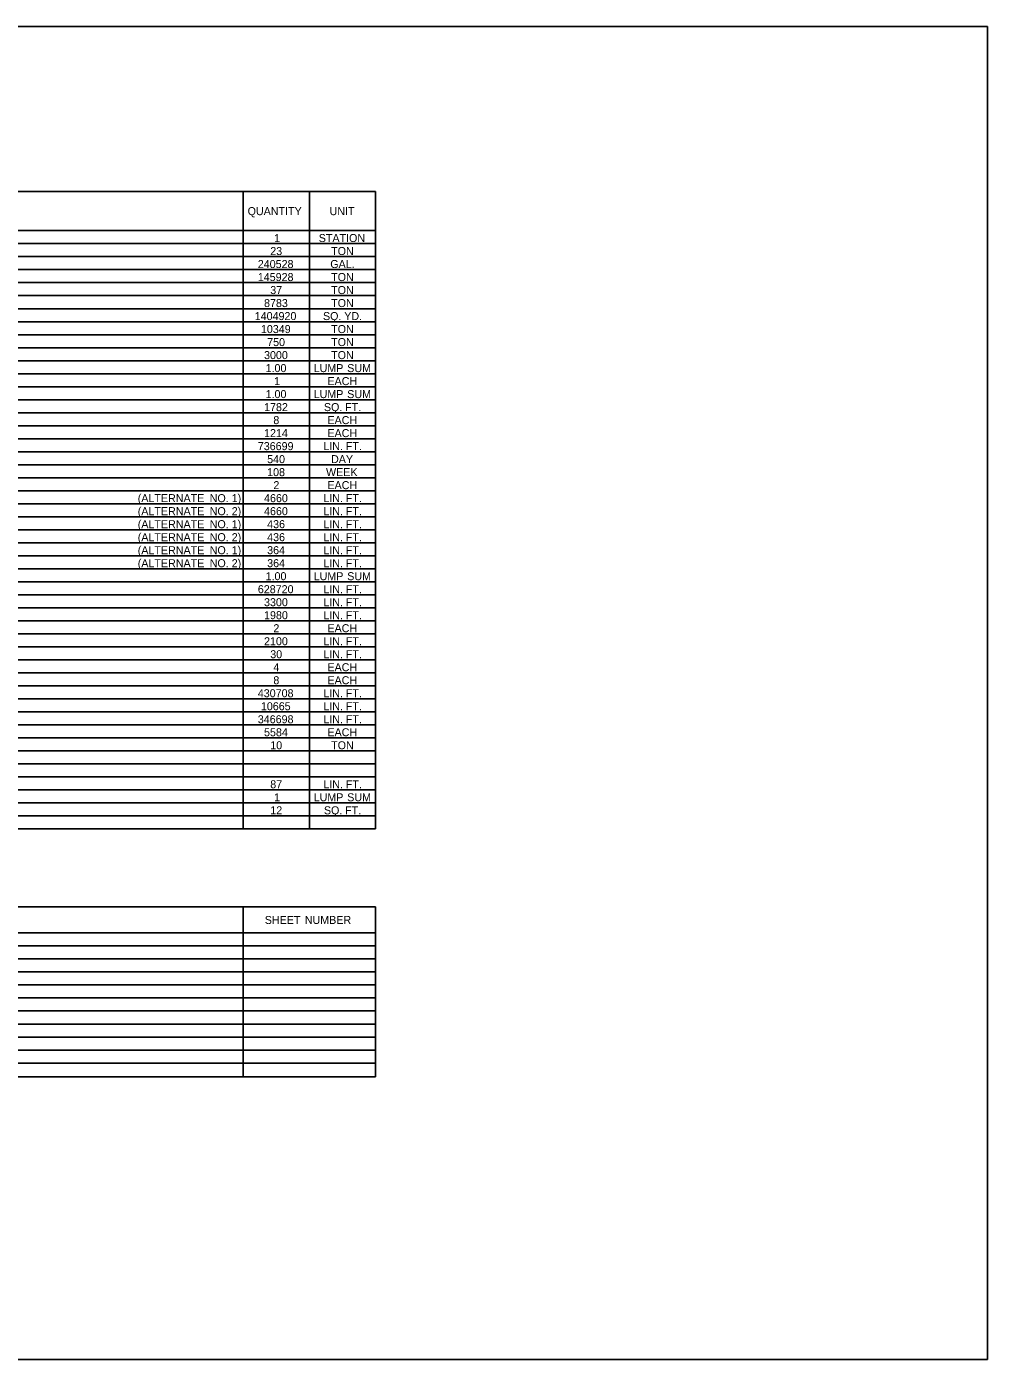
# Model space of a CAD drawing. Extents: x 2261867 to 2275370, y -3124789 to -3122260.
# Drawn here: x 2274649 to 2275370, y -3124789 to -3123790 of the extents above; entities that cross this region are included whole.
import ezdxf

# ---------------------------------------------------------------- set-up
doc = ezdxf.new("R2010")
doc.units = 0
doc.layers.add('Default', color=7, linetype='Continuous')
doc.layers.add('DSN_DRFT_Named-Boundary', color=7, linetype='Continuous')

msp = doc.modelspace()

# ---------------------------------------------------------------- linework, layer by layer
at = {"layer": 'Default'}
for p, q in [((2274241.54, -3123913.99), (2274910.87, -3123913.99)), ((2274811.42, -3123913.99), (2274910.87, -3123913.99)), ((2274811.42, -3124391.74), (2274811.42, -3123913.99)), ((2274861.15, -3124391.74), (2274861.15, -3123913.99)), ((2274861.15, -3124342.99), (2274861.15, -3123913.99)), ((2274910.87, -3124391.74), (2274910.87, -3123913.99)), ((2274241.54, -3123943.24), (2274910.87, -3123943.24)), ((2274241.54, -3123943.24), (2274910.87, -3123943.24)), ((2274811.42, -3124342.99), (2274811.42, -3123943.24)), ((2274241.54, -3123952.99), (2274910.87, -3123952.99)), ((2274241.54, -3123962.74), (2274910.87, -3123962.74)), ((2274241.54, -3123972.49), (2274910.87, -3123972.49)), ((2274241.54, -3123982.24), (2274910.87, -3123982.24)), ((2274241.54, -3123991.99), (2274910.87, -3123991.99)), ((2274241.54, -3124001.74), (2274910.87, -3124001.74)), ((2274241.54, -3124011.49), (2274910.87, -3124011.49)), ((2274241.54, -3124021.24), (2274910.87, -3124021.24)), ((2274241.54, -3124030.99), (2274910.87, -3124030.99)), ((2274241.54, -3124040.74), (2274910.87, -3124040.74)), ((2274241.54, -3124050.49), (2274910.87, -3124050.49)), ((2274241.54, -3124060.24), (2274910.87, -3124060.24)), ((2274241.54, -3124069.99), (2274910.87, -3124069.99)), ((2274241.54, -3124079.74), (2274910.87, -3124079.74)), ((2274241.54, -3124089.49), (2274910.87, -3124089.49)), ((2274241.54, -3124099.24), (2274910.87, -3124099.24)), ((2274241.54, -3124108.99), (2274910.87, -3124108.99)), ((2274241.54, -3124118.74), (2274910.87, -3124118.74)), ((2274241.54, -3124128.49), (2274910.87, -3124128.49)), ((2274241.54, -3124138.24), (2274910.87, -3124138.24)), ((2274241.54, -3124147.99), (2274910.87, -3124147.99)), ((2274241.54, -3124157.74), (2274910.87, -3124157.74)), ((2274241.54, -3124167.49), (2274910.87, -3124167.49)), ((2274241.54, -3124177.24), (2274910.87, -3124177.24)), ((2274241.54, -3124186.99), (2274910.87, -3124186.99)), ((2274241.54, -3124196.74), (2274910.87, -3124196.74)), ((2274241.54, -3124206.49), (2274910.87, -3124206.49)), ((2274241.54, -3124216.24), (2274910.87, -3124216.24)), ((2274241.54, -3124225.99), (2274910.87, -3124225.99)), ((2274241.54, -3124235.74), (2274910.87, -3124235.74)), ((2274241.54, -3124245.49), (2274910.87, -3124245.49)), ((2274241.54, -3124255.24), (2274910.87, -3124255.24)), ((2274241.54, -3124264.99), (2274910.87, -3124264.99)), ((2274241.54, -3124274.74), (2274910.87, -3124274.74)), ((2274241.54, -3124284.49), (2274910.87, -3124284.49)), ((2274241.54, -3124294.24), (2274910.87, -3124294.24)), ((2274241.54, -3124303.99), (2274910.87, -3124303.99)), ((2274241.54, -3124313.74), (2274910.87, -3124313.74)), ((2274241.54, -3124323.49), (2274910.87, -3124323.49)), ((2274241.54, -3124333.24), (2274910.87, -3124333.24)), ((2274241.54, -3124342.99), (2274910.87, -3124342.99)), ((2274861.15, -3124342.99), (2274910.87, -3124342.99)), ((2274241.54, -3124352.74), (2274910.87, -3124352.74)), ((2274241.54, -3124352.74), (2274910.87, -3124352.74)), ((2274811.42, -3124391.74), (2274811.42, -3124352.74)), ((2274861.15, -3124391.74), (2274861.15, -3124352.74)), ((2274241.54, -3124362.49), (2274910.87, -3124362.49)), ((2274241.54, -3124372.24), (2274910.87, -3124372.24)), ((2274241.54, -3124381.99), (2274910.87, -3124381.99)), ((2274241.54, -3124391.74), (2274910.87, -3124391.74)), ((2274910.87, -3124391.74), (2274910.87, -3124381.99)), ((2274241.54, -3124450.24), (2274910.87, -3124450.24)), ((2274811.42, -3124450.24), (2274910.87, -3124450.24)), ((2274811.42, -3124469.74), (2274811.42, -3124450.24)), ((2274811.42, -3124577.48), (2274811.42, -3124450.24)), ((2274910.87, -3124577.48), (2274910.87, -3124450.24)), ((2274910.87, -3124577.48), (2274910.87, -3124450.24)), ((2274241.54, -3124469.74), (2274910.87, -3124469.74)), ((2274241.54, -3124479.49), (2274910.87, -3124479.49)), ((2274241.54, -3124489.24), (2274910.87, -3124489.24)), ((2274241.54, -3124498.99), (2274910.87, -3124498.99)), ((2274241.54, -3124508.74), (2274910.87, -3124508.74)), ((2274241.54, -3124518.49), (2274910.87, -3124518.49)), ((2274241.54, -3124528.24), (2274910.87, -3124528.24)), ((2274241.54, -3124537.99), (2274910.87, -3124537.99)), ((2274241.54, -3124547.74), (2274910.87, -3124547.74)), ((2274241.54, -3124557.49), (2274910.87, -3124557.49)), ((2274241.54, -3124567.24), (2274910.87, -3124567.24)), ((2274241.54, -3124577.48), (2274910.87, -3124577.48))]:
    msp.add_line(p, q, dxfattribs=at)
at = {"layer": 'DSN_DRFT_Named-Boundary'}
msp.add_lwpolyline([(2273744.64, -3124789.38), (2275369.64, -3124789.38), (2275369.64, -3123790.32), (2273744.64, -3123790.32)], close=True, dxfattribs=at)

# ---------------------------------------------------------------- texts
at = {"layer": 'Default'}
for s, p in [('QUANTITY', (2274814.85, -3123931.62)), ('UNIT', (2274876.32, -3123931.62)), ('1', (2274834.73, -3123951.79)), ('STATION', (2274868.19, -3123951.79)), ('23', (2274831.82, -3123961.54)), ('TON', (2274877.5, -3123961.54)), ('240528', (2274822.49, -3123971.29)), ('GAL.', (2274876.83, -3123971.29)), ('145928', (2274822.49, -3123981.04)), ('TON', (2274877.5, -3123981.04)), ('37', (2274831.82, -3123990.79)), ('TON', (2274877.5, -3123990.79)), ('8783', (2274827.16, -3124000.54)), ('TON', (2274877.5, -3124000.54)), ('1404920', (2274820.18, -3124010.29)), ('SQ.', (2274871.37, -3124010.29)), (' YD.', (2274885.08, -3124010.29)), ('10349', (2274824.82, -3124020.04)), ('TON', (2274877.5, -3124020.04)), ('750', (2274829.5, -3124029.79)), ('TON', (2274877.5, -3124029.79)), ('3000', (2274827.17, -3124039.54)), ('TON', (2274877.5, -3124039.54)), ('1.00', (2274828.33, -3124049.29)), ('LUMP', (2274864.38, -3124049.29)), (' SUM', (2274887.31, -3124049.29)), ('1', (2274834.73, -3124059.04)), ('EACH', (2274874.7, -3124059.04)), ('1.00', (2274828.33, -3124068.79)), ('LUMP', (2274864.38, -3124068.79)), (' SUM', (2274887.31, -3124068.79)), ('1782', (2274827.19, -3124078.54)), ('SQ.', (2274872.07, -3124078.54)), (' FT.', (2274885.78, -3124078.54)), ('1214', (2274827.17, -3124098.04)), ('8', (2274834.14, -3124088.29)), ('EACH', (2274874.7, -3124088.29)), ('EACH', (2274874.7, -3124098.04)), ('736699', (2274822.49, -3124107.79)), ('LIN.', (2274871.61, -3124107.79)), (' FT.', (2274886.25, -3124107.79)), ('540', (2274829.5, -3124117.54)), ('DAY', (2274877.42, -3124117.54)), ('108', (2274829.48, -3124127.29)), ('WEEK', (2274873.67, -3124127.29)), ('2', (2274834.18, -3124137.04)), ('EACH', (2274874.7, -3124137.04)), ('(ALTERNATE', (2274732.45, -3124146.79)), (' NO.', (2274784.18, -3124146.79)), (' 1)', (2274800.68, -3124146.79)), ('4660', (2274827.17, -3124146.79)), ('LIN.', (2274871.61, -3124146.79)), (' FT.', (2274886.25, -3124146.79)), ('(ALTERNATE', (2274732.45, -3124156.54)), (' NO.', (2274784.18, -3124156.54)), (' 2)', (2274800.68, -3124156.54)), ('4660', (2274827.17, -3124156.54)), ('LIN.', (2274871.61, -3124156.54)), (' FT.', (2274886.25, -3124156.54)), ('(ALTERNATE', (2274732.45, -3124166.29)), (' NO.', (2274784.18, -3124166.29)), (' 1)', (2274800.68, -3124166.29)), ('436', (2274829.49, -3124166.29)), ('LIN.', (2274871.61, -3124166.29)), (' FT.', (2274886.25, -3124166.29)), ('(ALTERNATE', (2274732.45, -3124176.04)), (' NO.', (2274784.18, -3124176.04)), (' 2)', (2274800.68, -3124176.04)), ('436', (2274829.49, -3124176.04)), ('LIN.', (2274871.61, -3124176.04)), (' FT.', (2274886.25, -3124176.04)), ('(ALTERNATE', (2274732.45, -3124185.79)), (' NO.', (2274784.18, -3124185.79)), (' 1)', (2274800.68, -3124185.79)), ('364', (2274829.5, -3124185.79)), ('LIN.', (2274871.61, -3124185.79)), (' FT.', (2274886.25, -3124185.79)), ('(ALTERNATE', (2274732.45, -3124195.54)), (' NO.', (2274784.18, -3124195.54)), (' 2)', (2274800.68, -3124195.54)), ('364', (2274829.5, -3124195.54)), ('LIN.', (2274871.61, -3124195.54)), (' FT.', (2274886.25, -3124195.54)), ('1.00', (2274828.33, -3124205.29)), ('LUMP', (2274864.38, -3124205.29)), (' SUM', (2274887.31, -3124205.29)), ('628720', (2274822.51, -3124215.04)), ('LIN.', (2274871.61, -3124215.04)), (' FT.', (2274886.25, -3124215.04)), ('3300', (2274827.17, -3124224.79)), ('LIN.', (2274871.61, -3124224.79)), (' FT.', (2274886.25, -3124224.79)), ('1980', (2274827.17, -3124234.54)), ('LIN.', (2274871.61, -3124234.54)), (' FT.', (2274886.25, -3124234.54)), ('2', (2274834.18, -3124244.29)), ('EACH', (2274874.7, -3124244.29)), ('2100', (2274827.17, -3124254.04)), ('LIN.', (2274871.61, -3124254.04)), (' FT.', (2274886.25, -3124254.04)), ('30', (2274831.83, -3124263.79)), ('LIN.', (2274871.61, -3124263.79)), (' FT.', (2274886.25, -3124263.79)), ('4', (2274834.16, -3124273.54)), ('EACH', (2274874.7, -3124273.54)), ('8', (2274834.14, -3124283.29)), ('EACH', (2274874.7, -3124283.29)), ('430708', (2274822.49, -3124293.04)), ('LIN.', (2274871.61, -3124293.04)), (' FT.', (2274886.25, -3124293.04)), ('10665', (2274824.8, -3124302.79)), ('LIN.', (2274871.61, -3124302.79)), (' FT.', (2274886.25, -3124302.79)), ('346698', (2274822.49, -3124312.54)), ('LIN.', (2274871.61, -3124312.54)), (' FT.', (2274886.25, -3124312.54)), ('5584', (2274827.17, -3124322.29)), ('EACH', (2274874.7, -3124322.29)), ('10', (2274831.83, -3124332.04)), ('TON', (2274877.5, -3124332.04)), ('87', (2274831.82, -3124361.29)), ('LIN.', (2274871.61, -3124361.29)), (' FT.', (2274886.25, -3124361.29)), ('1', (2274834.73, -3124371.04)), ('LUMP', (2274864.38, -3124371.04)), (' SUM', (2274887.31, -3124371.04)), ('12', (2274831.85, -3124380.79)), ('SQ.', (2274872.07, -3124380.79)), (' FT.', (2274885.78, -3124380.79)), ('SHEET', (2274827.72, -3124462.99)), (' NUMBER', (2274855.5, -3124462.99))]:
    msp.add_text(s, height=6, dxfattribs=at).set_placement(p)

doc.saveas('drawing.dxf')
